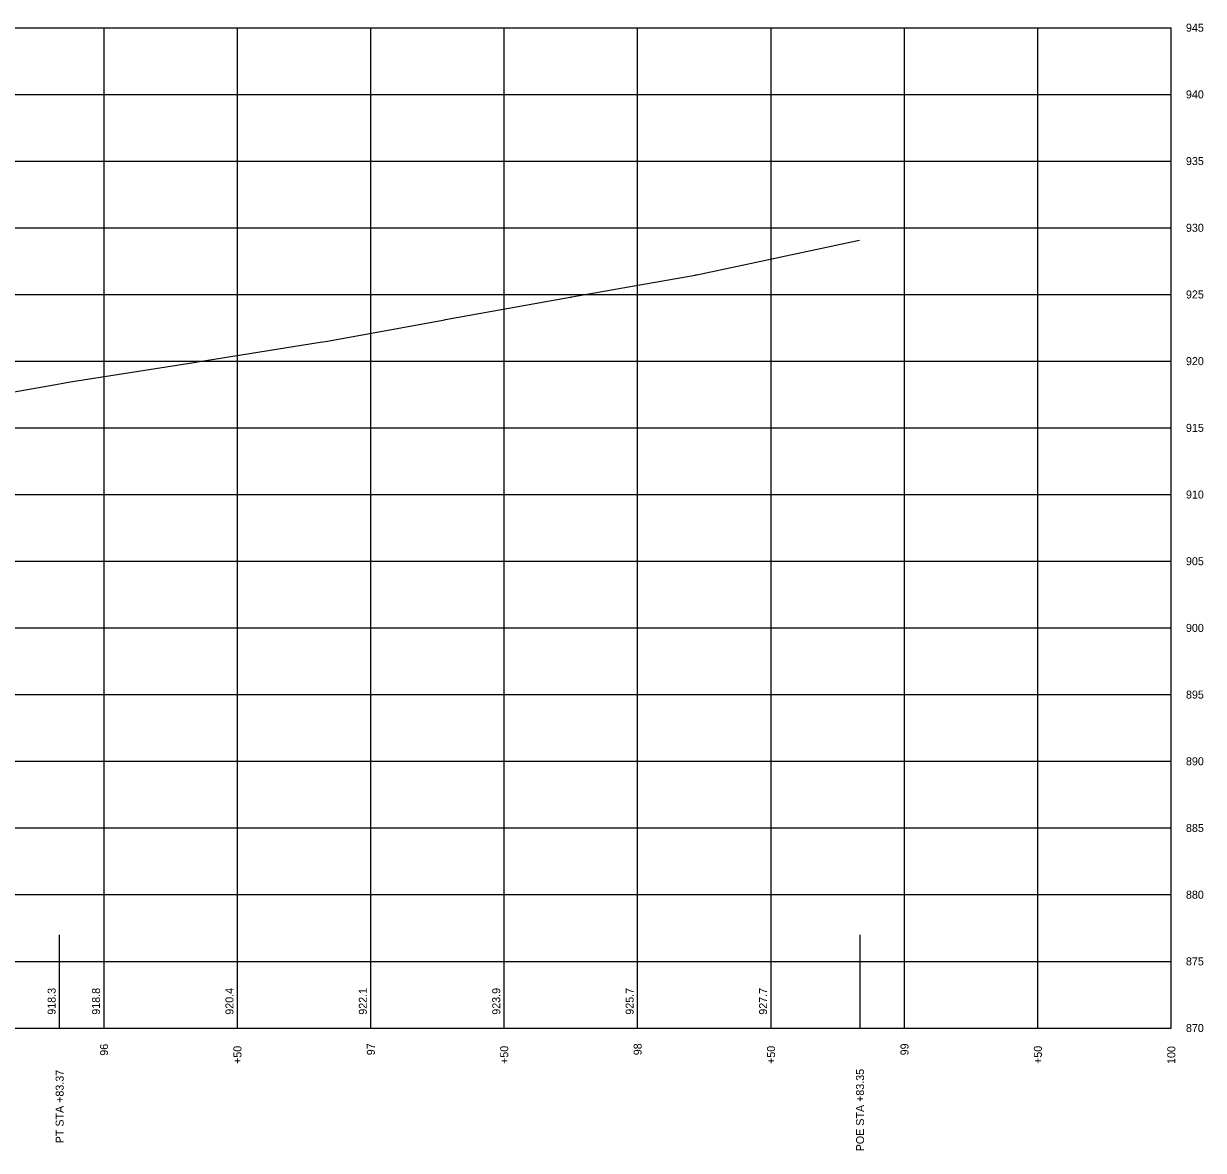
# Model space of a CAD drawing. Extents: x 76292 to 78417, y 50412 to 52585.
# Drawn here: x 77975.2 to 78417.4, y 51114.5 to 51536.9 of the extents above; entities that cross this region are included whole.
import ezdxf

# ---------------------------------------------------------------- set-up
doc = ezdxf.new("R2010")
doc.units = 0
for name, color, linetype in [('1', 7, 'Continuous'), ('2', 7, 'Continuous'), ('3', 7, 'Continuous'), ('33', 7, 'Continuous'), ('63', 7, 'Continuous')]:
    doc.layers.add(name, color=color, linetype=linetype)

msp = doc.modelspace()

# ---------------------------------------------------------------- linework, layer by layer
at = {"layer": '1'}
for p, q in [((76305.34, 51160.35), (78405.34, 51160.35)), ((78005.34, 51160.35), (78005.34, 51160.35)), ((78055.34, 51160.35), (78055.34, 51160.35)), ((78105.34, 51160.35), (78105.34, 51160.35)), ((78155.34, 51160.35), (78155.34, 51160.35)), ((78205.34, 51160.35), (78205.34, 51160.35)), ((78255.34, 51160.35), (78255.34, 51160.35)), ((78305.34, 51160.35), (78305.34, 51160.35)), ((78355.34, 51160.35), (78355.34, 51160.35)), ((78405.34, 51160.35), (78405.34, 51160.35))]:
    msp.add_line(p, q, dxfattribs=at)
for points in [[(77988.71, 51160.35), (77988.71, 51195.35)], [(77988.71, 51160.35), (77988.71, 51195.35)], [(77988.71, 51160.35), (77988.71, 51195.35)], [(77988.71, 51160.35), (77988.71, 51195.35)], [(78005.34, 51160.35), (78005.34, 51195.35)], [(78005.34, 51160.35), (78005.34, 51195.35)], [(78005.34, 51160.35), (78005.34, 51195.35)], [(78005.34, 51160.35), (78005.34, 51195.35)], [(78055.34, 51160.35), (78055.34, 51195.35)], [(78055.34, 51160.35), (78055.34, 51195.35)], [(78055.34, 51160.35), (78055.34, 51195.35)], [(78055.34, 51160.35), (78055.34, 51195.35)], [(78105.34, 51160.35), (78105.34, 51195.35)], [(78105.34, 51160.35), (78105.34, 51195.35)], [(78105.34, 51160.35), (78105.34, 51195.35)], [(78105.34, 51160.35), (78105.34, 51195.35)], [(78155.34, 51160.35), (78155.34, 51195.35)], [(78155.34, 51160.35), (78155.34, 51195.35)], [(78155.34, 51160.35), (78155.34, 51195.35)], [(78155.34, 51160.35), (78155.34, 51195.35)], [(78205.34, 51160.35), (78205.34, 51195.35)], [(78205.34, 51160.35), (78205.34, 51195.35)], [(78205.34, 51160.35), (78205.34, 51195.35)], [(78205.34, 51160.35), (78205.34, 51195.35)], [(78255.34, 51160.35), (78255.34, 51195.35)], [(78255.34, 51160.35), (78255.34, 51195.35)], [(78255.34, 51160.35), (78255.34, 51195.35)], [(78255.34, 51160.35), (78255.34, 51195.35)], [(78288.69, 51160.35), (78288.69, 51195.35)], [(78288.69, 51160.35), (78288.69, 51195.35)], [(78288.69, 51160.35), (78288.69, 51195.35)], [(78288.69, 51160.35), (78288.69, 51195.35)], [(78305.34, 51160.35), (78305.34, 51195.35)], [(78305.34, 51160.35), (78305.34, 51195.35)], [(78305.34, 51160.35), (78305.34, 51195.35)], [(78305.34, 51160.35), (78305.34, 51195.35)], [(78355.34, 51160.35), (78355.34, 51195.35)], [(78355.34, 51160.35), (78355.34, 51195.35)], [(78355.34, 51160.35), (78355.34, 51195.35)], [(78355.34, 51160.35), (78355.34, 51195.35)], [(78405.34, 51160.35), (78405.34, 51195.35)], [(78405.34, 51160.35), (78405.34, 51195.35)], [(78405.34, 51160.35), (78405.34, 51195.35)], [(78405.34, 51160.35), (78405.34, 51195.35)]]:
    msp.add_lwpolyline(points, dxfattribs=at)
at = {"layer": '2'}
msp.add_lwpolyline([(77969.49, 51398.5), (77975.9, 51399.61), (77982.31, 51400.73), (77988.71, 51401.86), (77992.61, 51402.55), (77992.63, 51402.55), (77992.64, 51402.55), (77993.59, 51402.71), (78039.06, 51409.87), (78039.71, 51409.97), (78040.36, 51410.07), (78086.34, 51417.45), (78087.33, 51417.59), (78088.3, 51417.75), (78133.06, 51425.89), (78133.19, 51425.91), (78133.33, 51425.94), (78180.03, 51434.29), (78180.36, 51434.35), (78180.67, 51434.4), (78204.07, 51438.6), (78226.89, 51442.62), (78227.18, 51442.68), (78227.55, 51442.76), (78287.25, 51455.49), (78288.5, 51455.75)], dxfattribs=at)
at = {"layer": '63'}
for p, q in [((76305.34, 51535.35), (78405.34, 51535.35)), ((76305.34, 51535.35), (78405.34, 51535.35)), ((78005.34, 51160.35), (78005.34, 51535.35)), ((78055.34, 51160.35), (78055.34, 51535.35)), ((78105.34, 51160.35), (78105.34, 51535.35)), ((78155.34, 51160.35), (78155.34, 51535.35)), ((78205.34, 51160.35), (78205.34, 51535.35)), ((78255.34, 51160.35), (78255.34, 51535.35)), ((78305.34, 51160.35), (78305.34, 51535.35)), ((78355.34, 51160.35), (78355.34, 51535.35)), ((78405.34, 51160.35), (78405.34, 51535.35)), ((78405.34, 51535.35), (78405.34, 51535.35)), ((78405.34, 51535.35), (78405.34, 51535.35)), ((76305.34, 51510.35), (78405.34, 51510.35)), ((78405.34, 51510.35), (78405.34, 51510.35)), ((76305.34, 51485.35), (78405.34, 51485.35)), ((78405.34, 51485.35), (78405.34, 51485.35)), ((76305.34, 51460.35), (78405.34, 51460.35)), ((78405.34, 51460.35), (78405.34, 51460.35)), ((76305.34, 51435.35), (78405.34, 51435.35)), ((78405.34, 51435.35), (78405.34, 51435.35)), ((76305.34, 51410.35), (78405.34, 51410.35)), ((78405.34, 51410.35), (78405.34, 51410.35)), ((76305.34, 51385.35), (78405.34, 51385.35)), ((78405.34, 51385.35), (78405.34, 51385.35)), ((76305.34, 51360.35), (78405.34, 51360.35)), ((78405.34, 51360.35), (78405.34, 51360.35)), ((76305.34, 51335.35), (78405.34, 51335.35)), ((78405.34, 51335.35), (78405.34, 51335.35)), ((76305.34, 51310.35), (78405.34, 51310.35)), ((78405.34, 51310.35), (78405.34, 51310.35)), ((76305.34, 51285.35), (78405.34, 51285.35)), ((78405.34, 51285.35), (78405.34, 51285.35)), ((76305.34, 51260.35), (78405.34, 51260.35)), ((78405.34, 51260.35), (78405.34, 51260.35)), ((76305.34, 51235.35), (78405.34, 51235.35)), ((78405.34, 51235.35), (78405.34, 51235.35)), ((76305.34, 51210.35), (78405.34, 51210.35)), ((78405.34, 51210.35), (78405.34, 51210.35)), ((76305.34, 51185.35), (78405.34, 51185.35)), ((78405.34, 51185.35), (78405.34, 51185.35)), ((78405.34, 51160.35), (78405.34, 51160.35))]:
    msp.add_line(p, q, dxfattribs=at)

# ---------------------------------------------------------------- texts
at = {"layer": '1'}
for s, p in [('96', (78006.84, 51149.98)), ('+50', (78056.84, 51146.89)), ('97', (78106.84, 51150.15)), ('+50', (78156.84, 51146.89)), ('98', (78206.84, 51150.15)), ('+50', (78256.84, 51146.89)), ('99', (78306.84, 51150.12)), ('+50', (78356.84, 51146.89)), ('100', (78406.84, 51146.89))]:
    msp.add_text(s, height=3, rotation=90, dxfattribs=at).set_placement(p)
at = {"layer": '3'}
for s, p in [('918.3', (77987.21, 51165.35)), ('918.8', (78003.84, 51165.35)), ('920.4', (78053.84, 51165.35)), ('922.1', (78103.84, 51165.35)), ('923.9', (78153.84, 51165.35)), ('925.7', (78203.84, 51165.35)), ('927.7', (78253.84, 51165.35))]:
    msp.add_text(s, height=3, rotation=90, dxfattribs=at).set_placement(p)
at = {"layer": '33'}
for s, p in [('PT STA +83.37', (77990.21, 51117.15)), ('POE STA +83.35', (78290.19, 51114.15))]:
    msp.add_text(s, height=3, rotation=90, dxfattribs=at).set_placement(p)
at = {"layer": '63'}
for s, p in [('945', (78410.84, 51533.85)), ('945', (78410.84, 51533.85)), ('940', (78410.84, 51508.85)), ('935', (78410.84, 51483.85)), ('930', (78410.84, 51458.85)), ('925', (78410.84, 51433.85)), ('920', (78410.84, 51408.85)), ('915', (78410.84, 51383.85)), ('910', (78410.84, 51358.85)), ('905', (78410.84, 51333.85)), ('900', (78410.84, 51308.85)), ('895', (78410.84, 51283.85)), ('890', (78410.84, 51258.85)), ('885', (78410.84, 51233.85)), ('880', (78410.84, 51208.85)), ('875', (78410.84, 51183.85)), ('870', (78410.84, 51158.85))]:
    msp.add_text(s, height=3, dxfattribs=at).set_placement(p)

doc.saveas('drawing.dxf')
